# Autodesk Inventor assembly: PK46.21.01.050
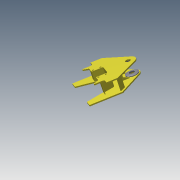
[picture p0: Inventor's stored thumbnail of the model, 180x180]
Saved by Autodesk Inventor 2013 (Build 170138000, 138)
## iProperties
Created: 2005-04
Part Number: PK46.21.01.050
Document SubType Name: Assembly
Designer: salex
Manufacturer: Standard
Standards Organization: Custom
Author: salex
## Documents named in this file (9)
- C:\Product Design Suite 2013\Data\Assy, Chassis, Front\PK46.21.01.050.iam
- C:\Product Design Suite 2013\Data\Assy, Chassis, Front\PK46.21.01.011.ipt
- C:\Product Design Suite 2013\Data\Assy, Chassis, Front\PK46.21.01.012.ipt
- C:\Product Design Suite 2013\Data\Assy, Chassis, Front\PK46.21.01.013.ipt
- C:\Product Design Suite 2013\Data\Assy, Chassis, Front\PK46.21.01.014.ipt
- C:\Product Design Suite 2013\Data\Assy, Chassis, Front\PK46.21.01.015.ipt
- C:\Product Design Suite 2013\Data\Assy, Chassis, Front\PK46.21.01.016.ipt
- C:\Product Design Suite 2013\Data\Assy, Chassis, Front\PK46.21.01.015-02.ipt
- C:\Product Design Suite 2013\Data\Assy, Chassis, Front\PK46.21.01.015-01.ipt
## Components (12 placed, 8 different names)
1. PK46.21.01.011:1 — Mate:3, Insert:2, Angle:2, Flush:3, Mate:29, Mate:31, Flush:10, Flush:11, Mate:37, Mate:40
2. PK46.21.01.012:1 — Mate:3, Insert:1, Mate:4, Mate:5, Angle:1, Mate:6, Mate:7, Angle:2, Mate:10, Mate:11, Mate:30, Mate:33, Mate:34, Mate:35, Mate:38, Flush:9
3. PK46.21.01.013:1 — Insert:2
4. PK46.21.01.013:2 — Insert:1
5. PK46.21.01.014:1 — Mate:4, Angle:1, Mate:6, Mate:8
6. PK46.21.01.014:2 — Mate:5, Mate:9, Mate:10
7. PK46.21.01.015:1 — Mate:35, Mate:36, Mate:37
8. PK46.21.01.015:2 — Mate:38, Mate:39, Mate:40
9. PK46.21.01.015-02:1 — Mate:7, Mate:8, Mate:9, Mate:11, Flush:3, Mate:29, Mate:36, Mate:39
10. PK46.21.01.016:1 — Mate:30, Mate:31, Mate:32, Flush:9
11. PK46.21.01.015-01:3 — Flush:11, Flush:12, Mate:34
12. PK46.21.01.015-01:4 — Mate:32, Mate:33, Flush:10, Flush:12
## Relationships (30: Mate 21, Flush 5, Insert 2, Angle 2)
- Mate:3: PK46.21.01.011:1 ↔ PK46.21.01.012:1
- Insert:1: PK46.21.01.012:1 ↔ PK46.21.01.013:2
- Insert:2: PK46.21.01.011:1 ↔ PK46.21.01.013:1
- Mate:4: PK46.21.01.012:1 ↔ PK46.21.01.014:1
- Mate:5: PK46.21.01.012:1 ↔ PK46.21.01.014:2
- Angle:1: PK46.21.01.012:1 ↔ PK46.21.01.014:1
- Mate:6: PK46.21.01.012:1 ↔ PK46.21.01.014:1
- Mate:7: PK46.21.01.012:1 ↔ PK46.21.01.015-02:1
- Mate:8: PK46.21.01.014:1 ↔ PK46.21.01.015-02:1
- Mate:9: PK46.21.01.014:2 ↔ PK46.21.01.015-02:1
- Angle:2: PK46.21.01.011:1 ↔ PK46.21.01.012:1
- Mate:10: PK46.21.01.012:1 ↔ PK46.21.01.014:2
- Mate:11: PK46.21.01.012:1 ↔ PK46.21.01.015-02:1
- Flush:3: PK46.21.01.011:1 ↔ PK46.21.01.015-02:1
- Mate:29: PK46.21.01.011:1 ↔ PK46.21.01.015-02:1
- Mate:30: PK46.21.01.012:1 ↔ PK46.21.01.016:1
- Mate:31: PK46.21.01.011:1 ↔ PK46.21.01.016:1
- Mate:32: PK46.21.01.016:1 ↔ PK46.21.01.015-01:4
- Mate:33: PK46.21.01.012:1 ↔ PK46.21.01.015-01:4
- Flush:10: PK46.21.01.011:1 ↔ PK46.21.01.015-01:4
- Flush:11: PK46.21.01.011:1 ↔ PK46.21.01.015-01:3
- Flush:12: PK46.21.01.015-01:3 ↔ PK46.21.01.015-01:4
- Mate:34: PK46.21.01.012:1 ↔ PK46.21.01.015-01:3
- Mate:35: PK46.21.01.012:1 ↔ PK46.21.01.015:1
- Mate:36: PK46.21.01.015:1 ↔ PK46.21.01.015-02:1
- Mate:37: PK46.21.01.011:1 ↔ PK46.21.01.015:1
- Mate:38: PK46.21.01.012:1 ↔ PK46.21.01.015:2
- Mate:39: PK46.21.01.015:2 ↔ PK46.21.01.015-02:1
- Mate:40: PK46.21.01.011:1 ↔ PK46.21.01.015:2
- Flush:9: PK46.21.01.012:1 ↔ PK46.21.01.016:1
